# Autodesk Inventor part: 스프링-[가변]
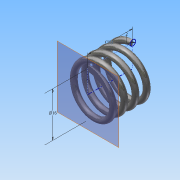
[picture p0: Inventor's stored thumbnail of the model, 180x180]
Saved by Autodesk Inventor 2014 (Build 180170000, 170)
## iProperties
Created: 2015-05
Part Number: 스프링-[가변]
Material: 강철, 탄소
Document SubType Name: Modeling
Designer: Administrator
Density: 7.87 g/cm^3
Appearance: 반연마
Mass: 4.75928 g
Surface Area: 12.5765 cm^2
Volume: 0.604738 cm^3
Author: Administrator
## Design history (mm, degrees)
sketch "스케치2"
  geometry: L1 (0, 0)-(8, 0); L2 (8, 0)-(8, 16); L3 (8, 16)-(0, 16); L4 (0, 16)-(0, 0); C1 r 1 at (8, 0)
  constraints: 8 end point, 2 parallel, 1 centre point, 1 coincident, 1 horizontal, 1 perpendicular
  dimensions: "d0" = 16 diameter of L2 L4; "d1" = 16 distance between parallel lines of L1 L3 (derived); "d2" = 2 diameter of C1
feature "코일1" pitch "d3" = 10; turns "d5" = 4; dims "d4" = 16 (= d1), "d6" = 0, angle "d7" = 90 deg, angle "d8" = 90 deg, "d9" = 0, "d10" = 0
sketch "스케치3"
  geometry: L1 (0, 9)-(0, 7) reference; 1 further point
  constraints: 1 vertical alignment
extrude "돌출1" cut sketch "스케치3" stored distance "d11" = 10; taper "d12" = 0 deg
node "작업 평면1"
sketch "스케치4"
  geometry: L1 (0, 9)-(0, 7) reference; 1 further point
  constraints: 1 vertical alignment
extrude "돌출2" cut sketch "스케치4" stored distance "d13" = 10; taper "d14" = 0 deg
node "솔리드1"
node "절단 모서리 투영1"
node "절단 모서리 투영2"
